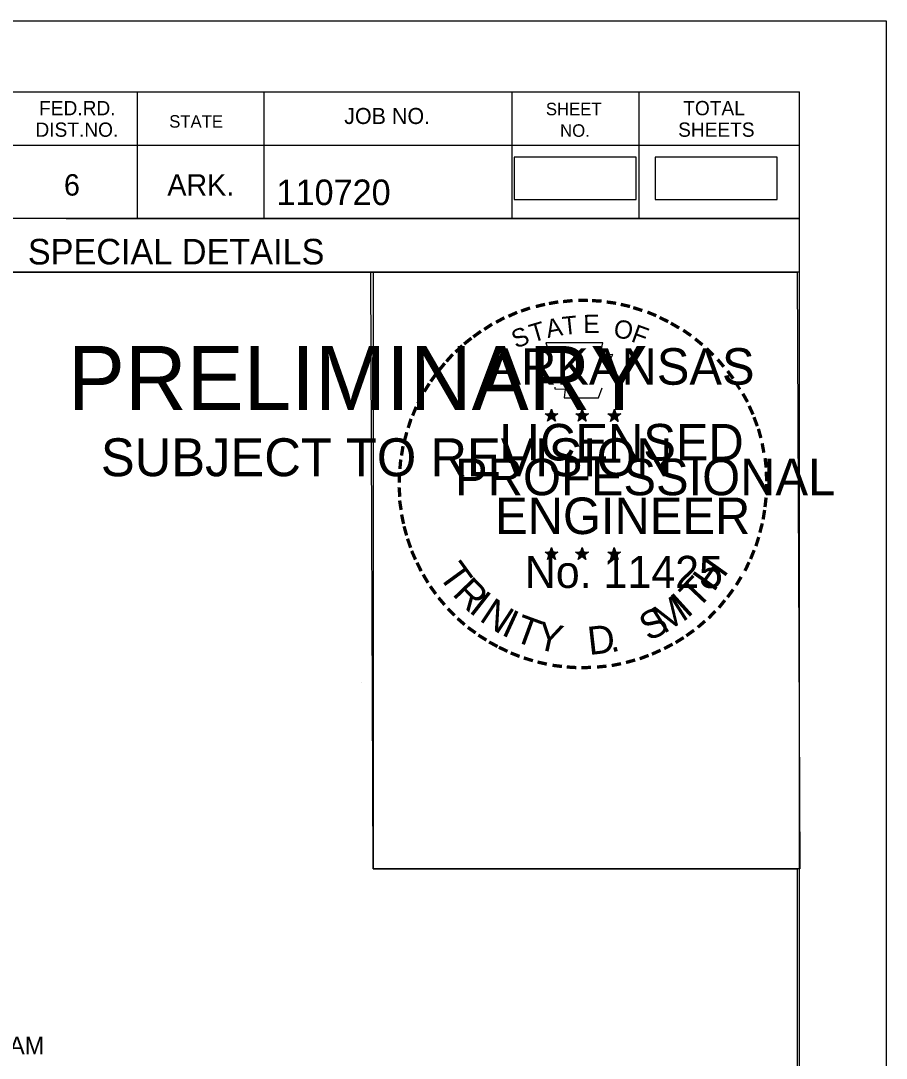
# Model space of a CAD drawing. Extents: x 1375738 to 1375905, y 380661 to 380875.
# Drawn here: x 1375881.2 to 1375904.89, y 380846.32 to 380874.73 of the extents above; entities that cross this region are included whole.
import ezdxf

# ---------------------------------------------------------------- set-up
doc = ezdxf.new("R2010")
doc.units = 0
for name, color, linetype in [('Default', 7, 'Continuous'), ('R_Border', 7, 'Continuous'), ('R_Border PE', 7, 'Continuous'), ('R_Border Prem', 7, 'Continuous'), ('R_Draft', 7, 'Continuous'), ('R_No Plot', 7, 'Continuous')]:
    doc.layers.add(name, color=color, linetype=linetype)

msp = doc.modelspace()

# ---------------------------------------------------------------- linework, layer by layer
at = {"layer": 'Default'}
for points in [[(1375894.697, 380869.836), (1375898.038, 380869.836), (1375898.038, 380870.991), (1375894.697, 380870.991)], [(1375898.56, 380869.836), (1375901.901, 380869.836), (1375901.901, 380870.991), (1375898.56, 380870.991)]]:
    msp.add_lwpolyline(points, close=True, dxfattribs=at)
at = {"layer": 'R_Border'}
for p, q in [((1375744.419, 380872.783), (1375902.509, 380872.783)), ((1375884.379, 380872.783), (1375884.379, 380869.313)), ((1375887.849, 380872.783), (1375887.849, 380869.313)), ((1375894.639, 380872.783), (1375894.639, 380869.313)), ((1375898.109, 380872.783), (1375898.109, 380869.313)), ((1375902.509, 380770.053), (1375902.509, 380872.783)), ((1375902.509, 380871.313), (1375880.959, 380871.313)), ((1375902.509, 380871.323), (1375902.509, 380871.323)), ((1375902.509, 380869.313), (1375880.959, 380869.313)), ((1375882.439, 380869.313), (1375902.509, 380869.313)), ((1375902.509, 380867.843), (1375871.189, 380867.843))]:
    msp.add_line(p, q, dxfattribs=at)
at = {"layer": 'R_Border PE'}
for p, q in [((1375895.726, 380864.097), (1375895.706, 380863.971)), ((1375895.726, 380863.915), (1375895.726, 380864.097)), ((1375895.726, 380864.097), (1375895.751, 380863.972)), ((1375896.561, 380864.097), (1375896.541, 380863.971)), ((1375896.561, 380863.915), (1375896.561, 380864.097)), ((1375896.561, 380864.097), (1375896.586, 380863.972)), ((1375897.443, 380864.091), (1375897.423, 380863.965)), ((1375897.443, 380863.909), (1375897.443, 380864.091)), ((1375897.443, 380864.091), (1375897.468, 380863.966)), ((1375895.552, 380863.97), (1375895.726, 380863.915)), ((1375895.552, 380863.97), (1375895.678, 380863.948)), ((1375895.552, 380863.97), (1375895.67, 380863.909)), ((1375895.618, 380863.766), (1375895.726, 380863.915)), ((1375895.618, 380863.766), (1375895.681, 380863.888)), ((1375895.618, 380863.766), (1375895.725, 380863.875)), ((1375895.833, 380863.766), (1375895.725, 380863.873)), ((1375895.9, 380863.97), (1375895.726, 380863.915)), ((1375895.833, 380863.766), (1375895.726, 380863.915)), ((1375895.9, 380863.97), (1375895.757, 380863.946)), ((1375895.833, 380863.766), (1375895.764, 380863.912)), ((1375895.9, 380863.97), (1375895.798, 380863.919)), ((1375896.387, 380863.97), (1375896.561, 380863.915)), ((1375896.387, 380863.97), (1375896.513, 380863.948)), ((1375896.387, 380863.97), (1375896.505, 380863.909)), ((1375896.453, 380863.766), (1375896.561, 380863.915)), ((1375896.453, 380863.766), (1375896.516, 380863.888)), ((1375896.453, 380863.766), (1375896.56, 380863.875)), ((1375896.668, 380863.766), (1375896.56, 380863.873)), ((1375896.735, 380863.97), (1375896.561, 380863.915)), ((1375896.668, 380863.766), (1375896.561, 380863.915)), ((1375896.735, 380863.97), (1375896.592, 380863.946)), ((1375896.668, 380863.766), (1375896.599, 380863.912)), ((1375896.735, 380863.97), (1375896.633, 380863.919)), ((1375897.269, 380863.964), (1375897.443, 380863.909)), ((1375897.269, 380863.964), (1375897.395, 380863.942)), ((1375897.269, 380863.964), (1375897.387, 380863.903)), ((1375897.335, 380863.76), (1375897.443, 380863.909)), ((1375897.335, 380863.76), (1375897.398, 380863.882)), ((1375897.335, 380863.76), (1375897.442, 380863.869)), ((1375897.55, 380863.76), (1375897.442, 380863.867)), ((1375897.617, 380863.964), (1375897.443, 380863.909)), ((1375897.55, 380863.76), (1375897.443, 380863.909)), ((1375897.617, 380863.964), (1375897.474, 380863.94)), ((1375897.55, 380863.76), (1375897.481, 380863.906)), ((1375897.617, 380863.964), (1375897.515, 380863.913)), ((1375895.55, 380860.184), (1375895.724, 380860.128)), ((1375895.55, 380860.184), (1375895.676, 380860.161)), ((1375895.55, 380860.184), (1375895.668, 380860.123)), ((1375895.616, 380859.98), (1375895.724, 380860.128)), ((1375895.616, 380859.98), (1375895.679, 380860.102)), ((1375895.616, 380859.98), (1375895.723, 380860.088)), ((1375895.724, 380860.311), (1375895.704, 380860.185)), ((1375895.724, 380860.128), (1375895.724, 380860.311)), ((1375895.724, 380860.311), (1375895.749, 380860.186)), ((1375895.898, 380860.184), (1375895.724, 380860.128)), ((1375895.831, 380859.98), (1375895.724, 380860.128)), ((1375895.898, 380860.184), (1375895.755, 380860.159)), ((1375895.831, 380859.98), (1375895.762, 380860.125)), ((1375895.898, 380860.184), (1375895.796, 380860.133)), ((1375896.384, 380860.184), (1375896.559, 380860.128)), ((1375896.384, 380860.184), (1375896.511, 380860.161)), ((1375896.384, 380860.184), (1375896.503, 380860.123)), ((1375896.451, 380859.98), (1375896.559, 380860.128)), ((1375896.451, 380859.98), (1375896.514, 380860.102)), ((1375896.451, 380859.98), (1375896.558, 380860.088)), ((1375896.559, 380860.311), (1375896.538, 380860.185)), ((1375896.559, 380860.128), (1375896.559, 380860.311)), ((1375896.559, 380860.311), (1375896.583, 380860.186)), ((1375896.732, 380860.184), (1375896.559, 380860.128)), ((1375896.665, 380859.98), (1375896.559, 380860.128)), ((1375896.732, 380860.184), (1375896.589, 380860.159)), ((1375896.665, 380859.98), (1375896.597, 380860.125)), ((1375896.732, 380860.184), (1375896.63, 380860.133)), ((1375897.268, 380860.179), (1375897.442, 380860.123)), ((1375897.268, 380860.179), (1375897.394, 380860.156)), ((1375897.268, 380860.179), (1375897.386, 380860.118)), ((1375897.334, 380859.975), (1375897.442, 380860.123)), ((1375897.334, 380859.975), (1375897.397, 380860.097)), ((1375897.442, 380860.306), (1375897.422, 380860.18)), ((1375897.442, 380860.123), (1375897.442, 380860.306)), ((1375897.442, 380860.306), (1375897.467, 380860.181)), ((1375897.616, 380860.179), (1375897.442, 380860.123)), ((1375897.549, 380859.975), (1375897.442, 380860.123)), ((1375897.616, 380860.179), (1375897.473, 380860.154)), ((1375897.549, 380859.975), (1375897.48, 380860.12)), ((1375897.616, 380860.179), (1375897.514, 380860.128)), ((1375895.831, 380859.98), (1375895.723, 380860.087)), ((1375896.665, 380859.98), (1375896.558, 380860.087)), ((1375897.334, 380859.975), (1375897.441, 380860.083)), ((1375897.549, 380859.975), (1375897.441, 380860.082))]:
    msp.add_line(p, q, dxfattribs=at)
for points in [[(1375895.572, 380865.909), (1375895.707, 380865.496)], [(1375897.328, 380865.448), (1375897.399, 380865.59), (1375897.056, 380865.578), (1375897.13, 380865.909), (1375895.572, 380865.909)], [(1375895.818, 380864.698), (1375895.818, 380864.654), (1375896.1, 380864.645), (1375896.073, 380864.408), (1375897.008, 380864.408), (1375897.108, 380864.676)], [(1375895.726, 380864.097), (1375895.833, 380863.766), (1375895.552, 380863.97), (1375895.9, 380863.97), (1375895.618, 380863.766), (1375895.726, 380864.097)], [(1375896.561, 380864.097), (1375896.668, 380863.766), (1375896.387, 380863.97), (1375896.735, 380863.97), (1375896.453, 380863.766), (1375896.561, 380864.097)], [(1375897.443, 380864.091), (1375897.55, 380863.76), (1375897.269, 380863.964), (1375897.617, 380863.964), (1375897.335, 380863.76), (1375897.443, 380864.091)], [(1375895.724, 380860.311), (1375895.831, 380859.98), (1375895.55, 380860.184), (1375895.898, 380860.184), (1375895.616, 380859.98), (1375895.724, 380860.311)], [(1375896.559, 380860.311), (1375896.665, 380859.98), (1375896.384, 380860.184), (1375896.732, 380860.184), (1375896.451, 380859.98), (1375896.559, 380860.311)], [(1375897.442, 380860.306), (1375897.549, 380859.975), (1375897.268, 380860.179), (1375897.616, 380860.179), (1375897.334, 380859.975), (1375897.442, 380860.306)]]:
    msp.add_lwpolyline(points, dxfattribs=at)
for centre, radius in [((1375895.726, 380863.914), 0.0861), ((1375895.726, 380863.914), 0.0723), ((1375895.726, 380863.914), 0.0579), ((1375895.726, 380863.914), 0.0495), ((1375895.726, 380863.914), 0.0374), ((1375895.726, 380863.914), 0.0248), ((1375895.726, 380863.914), 0.0148), ((1375896.561, 380863.914), 0.0861), ((1375896.561, 380863.914), 0.0723), ((1375896.561, 380863.914), 0.0579), ((1375896.561, 380863.914), 0.0495), ((1375896.561, 380863.914), 0.0374), ((1375896.561, 380863.914), 0.0248), ((1375896.561, 380863.914), 0.0148), ((1375897.443, 380863.908), 0.0861), ((1375897.443, 380863.908), 0.0723), ((1375897.443, 380863.908), 0.0579), ((1375897.443, 380863.908), 0.0495), ((1375897.443, 380863.908), 0.0374), ((1375897.443, 380863.908), 0.0248), ((1375897.443, 380863.908), 0.0148), ((1375895.724, 380860.128), 0.0861), ((1375895.724, 380860.128), 0.0723), ((1375895.724, 380860.128), 0.0579), ((1375895.724, 380860.128), 0.0495), ((1375895.724, 380860.128), 0.0374), ((1375895.724, 380860.128), 0.0248), ((1375895.724, 380860.128), 0.0148), ((1375896.558, 380860.128), 0.0861), ((1375896.558, 380860.128), 0.0723), ((1375896.558, 380860.128), 0.0579), ((1375896.558, 380860.128), 0.0495), ((1375896.558, 380860.128), 0.0374), ((1375896.558, 380860.128), 0.0248), ((1375896.558, 380860.128), 0.0148), ((1375897.442, 380860.123), 0.0861), ((1375897.442, 380860.123), 0.0723), ((1375897.442, 380860.123), 0.0579), ((1375897.442, 380860.123), 0.0495), ((1375897.442, 380860.123), 0.0374), ((1375897.442, 380860.123), 0.0248), ((1375897.442, 380860.123), 0.0148)]:
    msp.add_circle(centre, radius, dxfattribs=at)
at = {"layer": 'R_No Plot'}
for p, q in [((1375738.219, 380874.73), (1375904.885, 380874.73)), ((1375890.526, 380856.615), (1375890.526, 380856.615))]:
    msp.add_line(p, q, dxfattribs=at)
for points in [[(1375738.215, 380874.73), (1375904.885, 380874.73), (1375904.885, 380768.061), (1375738.215, 380768.061)], [(1375861.379, 380872.783), (1375871.189, 380872.783), (1375871.189, 380867.843), (1375879.245, 380867.843), (1375890.845, 380867.843), (1375890.845, 380851.508), (1375902.449, 380851.508), (1375902.509, 380770.053), (1375744.419, 380770.053), (1375744.419, 380872.783)], [(1375890.775, 380867.843), (1375902.449, 380867.843), (1375902.519, 380851.508), (1375890.845, 380851.508)]]:
    msp.add_lwpolyline(points, close=True, dxfattribs=at)

# ---------------------------------------------------------------- texts
at = {"layer": 'R_Border'}
for s, height, p in [('FED.RD.', 0.391, (1375881.699, 380872.143)), ('JOB NO.', 0.4396, (1375890.049, 380871.903)), ('SHEET', 0.342, (1375895.569, 380872.143)), ('TOTAL', 0.391, (1375899.329, 380872.143)), ('STATE', 0.342, (1375885.259, 380871.803)), ('DIST.NO.', 0.391, (1375881.599, 380871.553)), ('NO.', 0.342, (1375895.959, 380871.553)), ('SHEETS', 0.391, (1375899.189, 380871.553)), ('6', 0.586, (1375882.379, 380869.943)), ('ARK.', 0.5861, (1375885.209, 380869.943)), ('110720', 0.7, (1375888.197, 380869.683)), ('SPECIAL DETAILS', 0.7, (1375881.391, 380868.058))]:
    msp.add_text(s, height=height, dxfattribs=at).set_placement(p)
at = {"layer": 'R_Border PE'}
for s, height, rotation, p in [('-', 0.8, 19.1761, (1375894.946, 380866.473)), ('-', 0.8, 13.6302, (1375895.321, 380866.593)), ('-', 0.8, 10.2193, (1375895.66, 380866.674)), ('-', 0.8, 5.8968, (1375896.024, 380866.729)), ('-', 0.8, 0.1862, (1375896.41, 380866.765)), ('-', 0.8, 357.743, (1375896.772, 380866.759)), ('-', 0.8, 352.1617, (1375897.144, 380866.731)), ('-', 0.8, 347.2049, (1375897.503, 380866.674)), ('-', 0.8, 342.3362, (1375897.821, 380866.596)), ('-', 0.8, 28.7918, (1375894.312, 380866.18)), ('-', 0.8, 24.3072, (1375894.629, 380866.338)), ('T', 0.5, 6.0228, (1375896.044, 380866.122)), ('E', 0.5, 0.8323, (1375896.596, 380866.177)), ('-', 0.8, 337.8551, (1375898.188, 380866.485)), ('-', 0.8, 334.1211, (1375898.504, 380866.349)), ('-', 0.8, 34.0636, (1375894.014, 380865.995)), ('T', 0.5, 16.4036, (1375895.206, 380865.914)), ('A', 0.5, 11.2132, (1375895.619, 380866.039)), ('O', 0.5, 350.4515, (1375897.398, 380866.072)), ('F', 0.5, 340.0707, (1375897.875, 380865.958)), ('-', 0.8, 329.6409, (1375898.793, 380866.208)), ('-', 0.8, 38.9507, (1375893.487, 380865.608)), ('-', 0.8, 36.2317, (1375893.725, 380865.797)), ('S', 0.5, 21.594, (1375894.749, 380865.748)), ('-', 0.8, 325.8627, (1375899.115, 380866.027)), ('-', 0.8, 320.5297, (1375899.42, 380865.814)), ('-', 0.8, 42.9622, (1375893.27, 380865.4)), ('-', 0.8, 315.5786, (1375899.719, 380865.57)), ('-', 0.8, 48.4231, (1375893.046, 380865.161)), ('-', 0.8, 309.8797, (1375900.004, 380865.295)), ('-', 0.8, 50.6142, (1375892.845, 380864.918)), ('-', 0.8, 54.2325, (1375892.638, 380864.634)), ('-', 0.8, 306.6522, (1375900.266, 380864.994)), ('-', 0.8, 58.0706, (1375892.476, 380864.371)), ('-', 0.7, 303.6753, (1375900.509, 380864.71)), ('-', 0.8, 62.8713, (1375892.319, 380864.064)), ('-', 0.8, 299.6684, (1375900.669, 380864.407)), ('-', 0.8, 67.7743, (1375892.19, 380863.758)), ('-', 0.8, 294.6628, (1375900.831, 380864.101)), ('-', 0.8, 72.3945, (1375892.08, 380863.443)), ('-', 0.8, 290.5728, (1375900.959, 380863.812)), ('-', 0.8, 285.1233, (1375901.076, 380863.522)), ('-', 0.8, 75.461, (1375891.982, 380863.086)), ('-', 0.8, 81.2013, (1375891.916, 380862.73)), ('-', 0.8, 280.5493, (1375901.176, 380863.151)), ('-', 0.8, 85.1863, (1375891.878, 380862.384)), ('-', 0.8, 276.5962, (1375901.257, 380862.767)), ('-', 0.8, 274.3301, (1375901.287, 380862.406)), ('-', 0.8, 89.0622, (1375891.865, 380862.034)), ('-', 0.8, 94.1959, (1375891.883, 380861.671)), ('-', 0.8, 269.9407, (1375901.304, 380862.09)), ('-', 0.8, 98.9479, (1375891.919, 380861.338)), ('-', 0.8, 263.5172, (1375901.295, 380861.757)), ('-', 0.8, 260.9953, (1375901.259, 380861.43)), ('-', 0.8, 101.7149, (1375891.986, 380860.971)), ('-', 0.8, 255.7626, (1375901.204, 380861.091)), ('-', 0.8, 105.4578, (1375892.067, 380860.674)), ('-', 0.8, 109.0874, (1375892.175, 380860.358)), ('-', 0.8, 252.8681, (1375901.114, 380860.731)), ('-', 0.8, 114.0643, (1375892.302, 380860.06)), ('-', 0.8, 247.8887, (1375901.002, 380860.395)), ('-', 0.8, 115.7289, (1375892.454, 380859.751)), ('T', 0.77, 306.0406, (1375892.604, 380859.547)), ('H', 0.77, 54.6088, (1375900.164, 380859.065)), ('-', 0.8, 244.6197, (1375900.871, 380860.08)), ('-', 0.8, 120.4471, (1375892.633, 380859.458)), ('T', 0.77, 46.6444, (1375899.719, 380858.594)), ('-', 0.8, 239.0712, (1375900.674, 380859.704)), ('-', 0.8, 125.8934, (1375892.834, 380859.178)), ('R', 0.77, 314.005, (1375892.985, 380859.023)), ('-', 0.8, 130.7181, (1375893.065, 380858.902)), ('I', 0.77, 321.9694, (1375893.435, 380858.557)), ('M', 0.77, 32.6563, (1375898.796, 380857.931)), ('I', 0.77, 42.1136, (1375899.438, 380858.355)), ('-', 0.8, 233.8452, (1375900.473, 380859.378)), ('N', 0.77, 326.5002, (1375893.719, 380858.322)), ('-', 0.8, 231.2538, (1375900.258, 380859.095)), ('-', 0.8, 134.2238, (1375893.324, 380858.629)), ('-', 0.8, 138.9338, (1375893.586, 380858.397)), ('I', 0.77, 335.3603, (1375894.323, 380857.929)), ('T', 0.77, 339.8912, (1375894.654, 380857.765)), ('S', 0.77, 26.9312, (1375898.377, 380857.728)), ('-', 0.8, 225.7653, (1375900.019, 380858.813)), ('-', 0.8, 144.6463, (1375893.864, 380858.194)), ('Y', 0.77, 347.8556, (1375895.262, 380857.542)), ('D', 0.77, 6.3969, (1375896.754, 380857.363)), ('-', 0.8, 221.0851, (1375899.758, 380858.558)), ('-', 0.8, 148.0898, (1375894.145, 380858.009)), ('-', 0.8, 212.2491, (1375899.216, 380858.129)), ('-', 0.8, 215.7363, (1375899.483, 380858.322)), ('-', 0.8, 151.5704, (1375894.434, 380857.846)), ('-', 0.8, 154.6002, (1375894.695, 380857.723)), ('.', 0.77, 13.7642, (1375897.35, 380857.427)), ('-', 0.8, 204.2516, (1375898.625, 380857.796)), ('-', 0.8, 207.3568, (1375898.937, 380857.956)), ('-', 0.8, 158.5612, (1375895.007, 380857.596)), ('-', 0.8, 162.7983, (1375895.351, 380857.489)), ('-', 0.8, 195.4743, (1375897.977, 380857.539)), ('-', 0.8, 200.7184, (1375898.316, 380857.66)), ('-', 0.8, 167.5555, (1375895.708, 380857.407)), ('-', 0.8, 173.1155, (1375896.094, 380857.352)), ('-', 0.8, 176.5183, (1375896.468, 380857.326)), ('-', 0.8, 181.5918, (1375896.84, 380857.335)), ('-', 0.8, 185.8167, (1375897.245, 380857.373)), ('-', 0.8, 191.2858, (1375897.613, 380857.439))]:
    msp.add_text(s, height=height, rotation=rotation, dxfattribs=at).set_placement(p)
for s, height, p in [('ARKANSAS', 1, (1375893.998, 380864.765)), ('DWB', 0.005, (1375895.72, 380863.912)), ('DWB', 0.005, (1375896.555, 380863.912)), ('DWB', 0.005, (1375897.437, 380863.907)), ('LICENSED', 1, (1375894.297, 380862.691)), ('PROFESSIONAL', 1, (1375893.085, 380861.739)), ('ENGINEER', 1, (1375894.179, 380860.676)), ('No. 11425', 0.8785, (1375894.993, 380859.201)), ('DWB', 0.005, (1375895.718, 380860.126)), ('DWB', 0.005, (1375896.552, 380860.126)), ('DWB', 0.005, (1375897.436, 380860.121))]:
    msp.add_text(s, height=height, dxfattribs=at).set_placement(p)
at = {"layer": 'R_Border Prem'}
for s, height, p in [('PRELIMINARY', 1.75, (1375882.485, 380864.074)), ('DWB', 0.005, (1375882.858, 380864.999)), ('SUBJECT TO REVISION', 1.03756, (1375883.389, 380862.26))]:
    msp.add_text(s, height=height, dxfattribs=at).set_placement(p)
at = {"layer": 'R_Draft'}
msp.add_text('POLYETHYLENE FOAM', height=0.47916, dxfattribs=at).set_placement((1375874.717, 380846.435))

doc.saveas('drawing.dxf')
